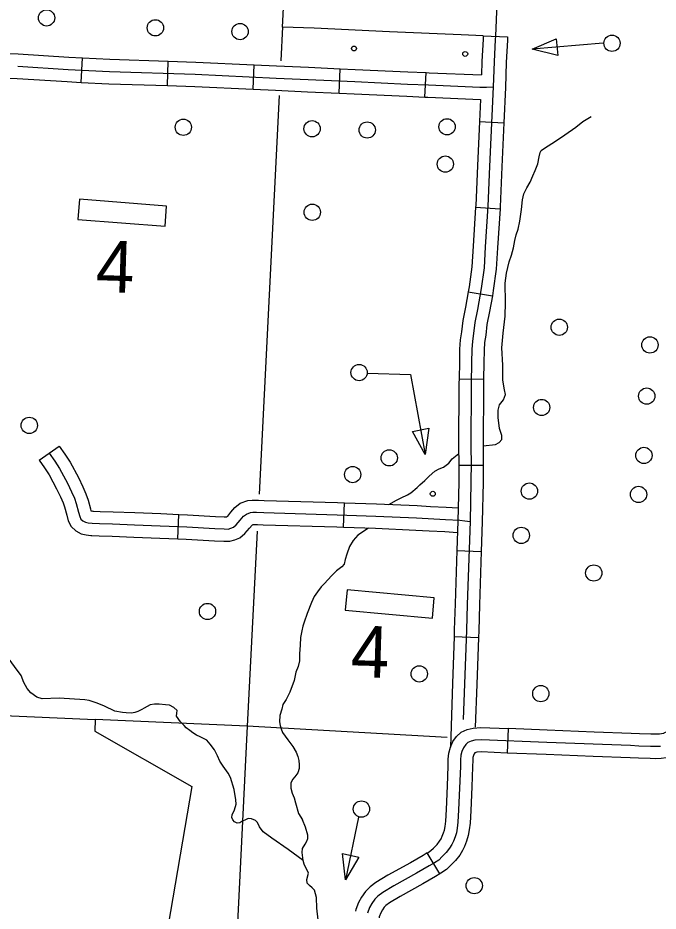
# Model space of a CAD drawing. Extents: x 653372 to 905732, y 627442 to 787275.
# Drawn here: x 673522 to 677453, y 779033 to 784516 of the extents above; entities that cross this region are included whole.
import ezdxf

# ---------------------------------------------------------------- set-up
doc = ezdxf.new("R2010")
doc.units = 0
for name, color, linetype in [('31', 7, 'Continuous'), ('32', 7, 'Continuous'), ('34', 7, 'Continuous'), ('35', 7, 'Continuous'), ('45', 7, 'Continuous'), ('5', 7, 'Continuous'), ('56', 7, 'Continuous'), ('57', 7, 'Continuous'), ('6', 7, 'Continuous')]:
    doc.layers.add(name, color=color, linetype=linetype)

msp = doc.modelspace()

# ---------------------------------------------------------------- linework, layer by layer
at = {"layer": '31'}
for p, q in [((676532.4, 780153.5), (676526.2, 780003.7)), ((676159.4, 779803.2), (676159.4, 779803.2)), ((676112.4, 779261.3), (676035.8, 779390.3))]:
    msp.add_line(p, q, dxfattribs=at)
for points in [[(676159.4, 779803.2), (676164.4, 779922.8), (676164.9, 779966.4), (676168, 780002.5), (676177.5, 780039.1), (676193.7, 780073.7), (676214.7, 780104.8), (676243.3, 780131.4), (676280.2, 780148.5), (676317.7, 780157), (676365.4, 780160.5), (676532.4, 780153.5)], [(677059.7, 780132.8), (676772.4, 780143.5), (676532.4, 780153.5)], [(677499.4, 780133.8), (677498.1, 780131.3), (677496.9, 780130.1), (677488.4, 780125.1), (677486.6, 780124.4), (677473.9, 780120.9), (677461.8, 780119.5), (677439, 780118.9), (677409, 780119.8), (677338.1, 780121.1), (677288.4, 780124.2), (677059.7, 780132.8)], [(677467.2, 780044.6), (677438.9, 780043.8), (677407.2, 780044.8), (677335.1, 780046.2), (677284.7, 780049.2), (676769.4, 780068.6), (676366.5, 780085.4), (676328.8, 780082.6), (676304.5, 780077.1), (676285.7, 780068.4), (676272, 780055.7), (676259.1, 780036.6), (676248.3, 780013.6), (676242.2, 779989.8), (676239.8, 779962.7), (676239.3, 779920.8), (676228.2, 779654.1), (676223.7, 779579.7), (676219.4, 779542.6), (676214.7, 779514), (676207, 779488.7), (676196.1, 779461.8), (676186.2, 779442), (676173.1, 779419.8), (676152.1, 779393.3), (676127.3, 779367.7), (676106.5, 779346.6), (676080.4, 779329.5), (676048, 779310.3), (675970.6, 779265.3), (675831.4, 779188.5), (675762.7, 779147.1), (675733.3, 779124.7), (675713.3, 779105.9), (675696.3, 779080), (675681.6, 779054.8), (675669.7, 779020.3)], [(677631.5, 780062.8), (677621.3, 780043.8), (677592, 780011.8), (677554.8, 779990.2), (677534.9, 779982.1), (677502.5, 779973.3), (677472.6, 779969.7), (677438.8, 779968.8), (677405.3, 779969.8), (677332.1, 779971.2), (677281, 779974.3), (677054.1, 779982.9)], [(676526.2, 780003.7), (676367.7, 780010.2), (676339.8, 780008.2), (676328.9, 780005.7), (676328.7, 780005.7), (676324.5, 779999.4), (676319.2, 779988.1), (676316.4, 779977.1), (676314.8, 779959), (676314.3, 779918.8), (676309.2, 779797)], [(677054.1, 779982.9), (676766.5, 779993.7), (676526.2, 780003.7)], [(676035.8, 779390.3), (676040.7, 779393.2), (676058.7, 779405), (676073.7, 779420.1), (676095.6, 779442.8), (676111.1, 779462.4), (676120.2, 779477.8), (676127.7, 779492.7), (676136.2, 779513.8), (676141.5, 779531.2), (676145.1, 779553), (676148.9, 779586.3), (676153.3, 779658), (676159.4, 779803.2)], [(676309.2, 779797), (676303.1, 779650.2), (676298.4, 779573.2), (676293.7, 779532.2), (676287.9, 779496.9), (676277.7, 779463.6), (676264.5, 779431), (676252.1, 779406.1), (676235.1, 779377.3), (676208.6, 779343.9), (676181, 779315.3), (676154.3, 779288.2), (676120.1, 779265.8), (676112.4, 779261.3)], [(676035.8, 779390.3), (676010, 779375), (675933.7, 779330.5), (675793.9, 779253.4), (675720.5, 779209.2), (675684.7, 779181.9), (675655.6, 779154.5), (675632.6, 779119.6), (675613.1, 779086.3), (675598.1, 779042.7), (675595.4, 779033.2)], [(676112.4, 779261.3), (676086, 779245.6), (676007.6, 779200), (675868.9, 779123.5), (675804.9, 779084.9), (675781.9, 779067.4), (675771.1, 779057.3), (675760, 779040.4), (675750, 779023.4), (675741.2, 778997.8), (675739.7, 778992.2)]]:
    msp.add_lwpolyline(points, dxfattribs=at)
at = {"layer": '32'}
for p, q in [((676379.4, 784406.7), (676529.2, 784400.3)), ((673911.2, 784120.6), (673918.7, 784270.4)), ((674440.1, 784100.4), (674445, 784250.3)), ((674966.5, 784078.1), (674973.6, 784227.9)), ((675494.2, 784054.5), (675500.9, 784204.3)), ((676021.6, 784030.4), (676028.3, 784180.3)), ((676355.8, 783879.4), (676505.6, 783872.7)), ((676333, 783353.7), (676482.7, 783343.4)), ((676287.5, 782835.7), (676435.4, 782810.3)), ((676230.9, 782300.9), (676380.9, 782297.6)), ((676229.7, 781771.7), (676379.7, 781770.9)), ((676217.8, 781246), (676367.7, 781240.9)), ((676200.4, 780718.4), (676350.3, 780713))]:
    msp.add_line(p, q, dxfattribs=at)
for points in [[(676379.4, 784406.7), (676378.5, 784386.3), (676370.9, 784249.4), (676367.9, 784165.9)], [(676454.3, 784403.5), (676453.4, 784382.7), (676445.8, 784246), (676440.3, 784092.4), (676418.6, 783604.2), (676408.7, 783361.4), (676391.5, 783110.1)], [(676529.2, 784400.3), (676528.3, 784379), (676520.7, 784242.6), (676515.3, 784089.4), (676505.6, 783872.7)], [(673384.7, 784297.2), (673412.9, 784298.4), (673524.8, 784295), (673834.4, 784274.7), (673918.7, 784270.4)], [(673918.7, 784270.4), (674087, 784261.9), (674445, 784250.3)], [(673521.2, 784220.1), (673830, 784199.8), (674083.9, 784187), (674611.5, 784169.9), (675107.3, 784146.6), (675303.7, 784138.1), (675590.3, 784125.3), (675914, 784110.4), (676043.4, 784104.5), (676359.4, 784091.2), (676399.5, 784091.9), (676440.3, 784092.4)], [(674445, 784250.3), (674614.5, 784244.8), (674973.6, 784227.9)], [(674973.6, 784227.9), (675110.7, 784221.5), (675307, 784213), (675500.9, 784204.3)], [(675500.9, 784204.3), (675593.7, 784200.2), (675917.4, 784185.3), (676028.3, 784180.3)], [(673402.9, 784148.6), (673517.6, 784145.1), (673825.7, 784124.9), (673911.2, 784120.6)], [(676028.3, 784180.3), (676046.7, 784179.5), (676367.9, 784165.9)], [(673911.2, 784120.6), (674080.8, 784112.1), (674440.1, 784100.4)], [(674440.1, 784100.4), (674608.6, 784094.9), (674966.5, 784078.1)], [(674966.5, 784078.1), (675103.9, 784071.6), (675300.4, 784063.1), (675494.2, 784054.5)], [(675494.2, 784054.5), (675586.9, 784050.3), (675910.6, 784035.4), (676021.6, 784030.4)], [(676021.6, 784030.4), (676040.1, 784029.6), (676361.9, 784016)], [(676361.9, 784016), (676355.8, 783879.4)], [(676355.8, 783879.4), (676343.7, 783607.4), (676333.8, 783365.5), (676333, 783353.7)], [(676505.6, 783872.7), (676493.6, 783601), (676483.6, 783357.3), (676482.7, 783343.4)], [(676333, 783353.7), (676316.7, 783114.7), (676309.9, 782989.1), (676292.7, 782865.8), (676287.5, 782835.7)], [(676482.7, 783343.4), (676466.4, 783105.6), (676459.4, 782974.7), (676440.9, 782842.7), (676435.4, 782810.3)], [(676391.5, 783110.1), (676384.7, 782981.9), (676366.8, 782854.2), (676345, 782727), (676328.5, 782646.4), (676320.5, 782579.5), (676313.1, 782531.6), (676309.5, 782479.7), (676308.1, 782400.6), (676305.3, 782272.4), (676303.4, 781874.9), (676304.8, 781787.7), (676304.1, 781665.5), (676298.9, 781424.3), (676281.6, 780916.4), (676276.8, 780757.3), (676264.9, 780427.6), (676256.9, 780209.9)], [(676287.5, 782835.7), (676271.3, 782740.9), (676254.4, 782658.3), (676246.2, 782589.7), (676238.5, 782540), (676234.6, 782482.9), (676233.1, 782402), (676230.9, 782300.9)], [(676435.4, 782810.3), (676418.7, 782713.2), (676402.6, 782634.4), (676394.8, 782569.3), (676387.7, 782523.3), (676384.5, 782476.4), (676383.1, 782399.1), (676380.9, 782297.6)], [(676230.9, 782300.9), (676230.3, 782273.4), (676228.4, 781874.5), (676229.8, 781787.3), (676229.7, 781771.7)], [(676380.9, 782297.6), (676380.3, 782271.4), (676378.4, 781875.3), (676379.8, 781788.1), (676379.7, 781770.9)], [(676229.7, 781771.7), (676229.1, 781666.6), (676223.9, 781426.4), (676217.8, 781246)], [(676379.7, 781770.9), (676379.1, 781664.5), (676373.8, 781422.2), (676367.7, 781240.9)], [(676217.8, 781246), (676206.6, 780918.8), (676201.9, 780759.8), (676200.4, 780718.4)], [(676367.7, 781240.9), (676356.6, 780914), (676351.8, 780754.8), (676350.3, 780713)], [(676200.4, 780718.4), (676190, 780430.3), (676177.5, 780039.1)], [(676350.3, 780713), (676339.9, 780424.8), (676330.2, 780161.9)]]:
    msp.add_lwpolyline(points, dxfattribs=at)
at = {"layer": '34'}
msp.add_lwpolyline([(676593.1, 786729.9), (676561.3, 786090.6), (676516.4, 785413.5), (676500.9, 785202.7), (676475.4, 784823.6), (676462.8, 784604.8), (676454.3, 784403.5)], dxfattribs=at)
at = {"layer": '35'}
for points in [[(676514, 782686), (676516.9, 782768.4), (676513.8, 782886.9), (676522.5, 782948.5), (676539, 783018.8), (676552.1, 783059), (676564.7, 783105.6), (676573.9, 783148.9), (676582, 783185.4), (676593.5, 783218.9), (676603.6, 783268.9), (676614, 783339.2), (676620.7, 783399.5), (676628.4, 783436.2), (676647.5, 783473.8), (676666.8, 783507.8), (676683.2, 783546), (676698.2, 783579.7), (676714.3, 783620.6), (676723.4, 783662.6), (676728.3, 783689.4), (676736.2, 783701.4), (676760.9, 783720.4), (676817.9, 783755.6), (676880.6, 783797.4), (676948.1, 783845.8), (676991.2, 783879.9), (677042.4, 783910.3)], [(676378.1, 781890), (676455.3, 781897.8), (676478.3, 781909.8), (676493.5, 781929), (676494.1, 781952.8), (676480.2, 781996), (676471.5, 782064.1), (676471.9, 782108.7), (676478.9, 782141), (676503.7, 782171.5), (676515.3, 782204.3), (676511, 782232.8), (676499.6, 782293.5), (676498.9, 782384.2), (676494.6, 782491.5), (676502.7, 782580.2), (676514, 782686)], [(675800.3, 781529.8), (675847.6, 781556.8), (675876.2, 781570.8), (675915, 781588.8), (675935.7, 781601.7), (675973, 781633.3), (675990.5, 781649.1), (676021.9, 781677), (676047.2, 781703.7), (676081.5, 781733.9), (676108.6, 781747.9), (676136.4, 781758.9), (676167.6, 781784), (676189.2, 781810.1), (676228.9, 781841.4)], [(675674.7, 781384.8), (675609, 781342), (675581.7, 781309.3), (675558.8, 781272.4), (675542.2, 781224.2), (675532, 781190.9), (675524.6, 781162.8), (675511.6, 781146.8), (675477.5, 781121.2), (675449.1, 781093.7), (675424.6, 781066.8), (675404.1, 781043.7), (675383.8, 781023.9), (675361.1, 780993), (675341.8, 780964.6), (675325.6, 780926.9), (675299.2, 780861.2), (675280.5, 780806.4), (675271.8, 780781.7), (675265.1, 780754.7), (675257.3, 780712.8), (675255.9, 780666.1), (675251.6, 780613.6), (675250.3, 780569.5), (675244, 780534.1), (675229.8, 780501), (675217.7, 780448.8), (675192.5, 780376.5), (675170.1, 780332.3), (675149.5, 780302), (675142, 780272.6), (675130.7, 780235.1), (675129.5, 780195), (675132.1, 780171.8), (675138.1, 780153.2), (675147.3, 780130.6), (675163.7, 780107.7), (675180.1, 780084.8), (675210.5, 780044.4), (675231.2, 780009.5), (675241.6, 779982.9), (675248.1, 779957), (675249.9, 779931.7), (675249.9, 779909.2), (675240.6, 779882.5), (675223.4, 779858), (675207.7, 779840.8), (675198.5, 779817.9), (675198.2, 779789), (675207.2, 779757.8), (675218.1, 779727.8), (675225.8, 779697.9), (675245.5, 779631.6), (675270, 779593.3)], [(673933.7, 780329.9), (673775, 780340.4), (673670.9, 780336), (673638.1, 780346.1), (673601.3, 780372.8), (673579.5, 780400.5), (673559.5, 780435.8), (673542.7, 780480), (673500.7, 780535.5), (673451.5, 780601.7), (673406.7, 780664.9), (673349.8, 780726.8), (673303, 780770.4), (673284.3, 780802.6), (673281.5, 780818.2)], [(675273.6, 779343.8), (675180.9, 779411.7), (675081.5, 779481.1), (675027.7, 779519.7), (675004.9, 779549.8), (674992.4, 779577.7), (674980.5, 779590.4), (674956.1, 779600.6), (674935.3, 779602.2), (674922.8, 779596), (674897.7, 779582.5), (674885.2, 779575.3), (674868, 779572.9), (674853.1, 779581.9), (674842.1, 779594.6), (674834.9, 779608.1), (674838.3, 779625.1), (674851.5, 779654.1), (674862, 779688.9), (674860.9, 779715.5), (674851, 779778.9), (674827.6, 779853.6), (674813.2, 779879.6), (674782.3, 779923.3), (674762.3, 779954.2), (674748.1, 779986.9), (674729.3, 780022.6), (674701.9, 780057.6), (674681.8, 780082.8), (674641.6, 780104), (674619.2, 780114.1), (674595.8, 780127.2), (674577.3, 780141.9), (674556, 780157.8), (674543.1, 780172.4), (674521.5, 780194.6), (674496.9, 780229.5), (674498.5, 780249.4), (674499.9, 780265.5), (674478.7, 780284.1), (674452.5, 780297.3), (674427.9, 780299.9), (674390.1, 780302.9), (674361.6, 780302.8), (674334, 780298.9), (674298.3, 780280.1), (674283.8, 780271), (674258.8, 780258.5), (674240.6, 780253.3), (674220.5, 780248.3), (674186.5, 780250.2), (674164.7, 780251.8), (674116.6, 780259.9), (674054.9, 780291.2), (674009.9, 780310.6), (673984.5, 780317), (673960.1, 780325.3), (673933.7, 780329.9)], [(675365.1, 778980.6), (675358.7, 779051), (675355.9, 779117.5), (675343, 779161.6), (675329.3, 779177.2), (675311.7, 779191), (675298.8, 779204.6), (675296.6, 779226.5), (675307.3, 779266.9), (675280.5, 779320.8), (675273.6, 779343.8), (675268.4, 779393.3), (675270.1, 779417.9), (675287, 779444), (675296.1, 779463.6), (675302.3, 779479.1), (675301.9, 779499.1), (675287.3, 779547.9), (675270, 779593.3)]]:
    msp.add_lwpolyline(points, dxfattribs=at)
at = {"layer": '45'}
for p, q in [((673653.6, 781800.7), (673776.3, 781887)), ((675521.6, 781390.3), (675527, 781540.2)), ((674503.8, 781318.6), (674510.2, 781468.4))]:
    msp.add_line(p, q, dxfattribs=at)
for points in [[(673776.3, 781887), (673810.6, 781838.3), (673842.3, 781789.2), (673894.1, 781694.2), (673920.4, 781638.3), (673940.1, 781594.8), (673952.9, 781556.7), (673967, 781502.2), (673969.9, 781491.1), (673985, 781488.9), (673982.8, 781489)], [(673653.6, 781800.7), (673686.3, 781754.2), (673713.4, 781712.4), (673760.2, 781626.4), (673784.2, 781575.4), (673800.4, 781539.7), (673809, 781514.1), (673821.9, 781464.1), (673831.4, 781428.6), (673849.1, 781393.5), (673877.9, 781368.1), (673911, 781349.5), (673941.7, 781343.6), (673970.9, 781339.4), (673976.1, 781339.2)], [(673714.9, 781843.8), (673748.4, 781796.2), (673777.9, 781750.8), (673827.2, 781660.3), (673852.3, 781606.8), (673870.3, 781567.2), (673880.9, 781535.4), (673894.4, 781483.1), (673901.8, 781455.5), (673909.6, 781440.2), (673921.6, 781429.6), (673937.1, 781420.9), (673954.1, 781417.6), (673978, 781414.2), (674023.8, 781412.1), (674103.5, 781409.7), (674237.6, 781404.3), (674396.2, 781398.2), (674559.4, 781391.3), (674732.3, 781381.3), (674788, 781378.9), (674814, 781378.8), (674829.2, 781383.2), (674845.8, 781390.2), (674863.4, 781404.7), (674887.5, 781433.5), (674907.4, 781456.8), (674924.9, 781470.7), (674950.6, 781480.2), (674964.4, 781481.6)], [(674510.2, 781468.4), (674563.2, 781466.2), (674736.1, 781456.2), (674789.7, 781453.9), (674803.6, 781453.9), (674804.2, 781454), (674806.5, 781455), (674810.3, 781458.2), (674830.3, 781481.9), (674855.1, 781511.1), (674887.7, 781536.9), (674933.4, 781553.8), (674960.7, 781556.7), (674988.3, 781556.5), (674999.7, 781556)], [(674999.7, 781556), (675033.9, 781554.6), (675484.7, 781541.7), (675527, 781540.2)], [(675527, 781540.2), (675723.5, 781533.2), (675973.8, 781522.2), (676055.9, 781517.8)], [(676055.9, 781517.8), (676152, 781512.6), (676225.7, 781508.1)], [(673982.8, 781489), (674026.6, 781487.1), (674106.2, 781484.7), (674240.5, 781479.3), (674399.3, 781473.1), (674510.2, 781468.4)], [(674964.4, 781481.6), (674986.5, 781481.5), (675031.3, 781479.6), (675482.3, 781466.8), (675720.5, 781458.2), (675970.1, 781447.3), (676147.6, 781437.7), (676236.7, 781432.3), (676265.9, 781429.3), (676298.9, 781424.3)], [(674503.8, 781318.6), (674555.6, 781316.4), (674728.6, 781306.4), (674786.3, 781303.9), (674824.4, 781303.8), (674854.2, 781312.3), (674885.2, 781325.4), (674916.5, 781351.3), (674944.8, 781385), (674959.7, 781402.6), (674962.2, 781404.5), (674967.8, 781406.6), (674968.1, 781406.6), (674984.7, 781406.5), (674993.4, 781406.2)], [(674993.4, 781406.2), (675028.6, 781404.7), (675479.8, 781391.8), (675521.6, 781390.3)], [(675521.6, 781390.3), (675717.5, 781383.3), (675966.5, 781372.3), (676047.8, 781368)], [(676047.8, 781368), (676143.3, 781362.9), (676221.6, 781358.1)], [(673976.1, 781339.2), (674021, 781337.2), (674100.9, 781334.8), (674234.6, 781329.4), (674393.2, 781323.3), (674503.8, 781318.6)]]:
    msp.add_lwpolyline(points, dxfattribs=at)
at = {"layer": '5'}
for points in [[(675147.7, 784461.6), (675137.1, 784252.8)], [(675126.3, 784039.5), (675002.7, 781592.3)], [(674991.2, 781365), (674930.7, 780168.6)], [(674930.7, 780168.6), (673997.2, 780209.2)], [(674930.7, 780168.6), (674845, 778418.5)], [(676159, 780099.4), (674930.7, 780168.6)]]:
    msp.add_lwpolyline(points, dxfattribs=at)
at = {"layer": '56'}
for p, q in [((676680, 784324.8), (676828.3, 784388.1)), ((676828.3, 784388.1), (676836.7, 784286.4)), ((676836.7, 784286.4), (676680, 784324.8)), ((675946, 781978.4), (676046.3, 781996.9)), ((676023.9, 781837.2), (675946, 781978.4)), ((676046.3, 781996.9), (676023.9, 781837.2)), ((675533.2, 779226.2), (675515.1, 779386.5)), ((675515.1, 779386.5), (675614.8, 779365.3)), ((675614.8, 779365.3), (675533.2, 779226.2))]:
    msp.add_line(p, q, dxfattribs=at)
for points in [[(677116.8, 784360.6), (676680, 784324.8)], [(675668.5, 782336), (675933.2, 782327.8), (676023.9, 781837.2)], [(675614.5, 779609.2), (675533.2, 779226.2)]]:
    msp.add_lwpolyline(points, dxfattribs=at)
for centre, radius in [((673698.2, 784516.3), 50), ((674366.5, 784455.2), 50), ((674886.2, 784432.5), 50), ((677170.1, 784360.6), 50), ((675585.9, 784328.6), 15), ((676269, 784295), 15), ((674537.9, 783844.7), 50), ((675328.7, 783835.7), 50), ((675667, 783828.2), 50), ((676157.4, 783847.6), 50), ((676146.7, 783618.5), 50), ((675329.7, 783322.9), 50), ((676846.5, 782617.5), 50), ((677403.2, 782508.8), 50), ((675617.4, 782339.1), 50), ((677383.2, 782194.5), 50), ((676738.2, 782124.8), 50), ((673592, 782014.7), 50), ((675802.1, 781815.7), 50), ((677366, 781830.3), 50), ((675577.7, 781713), 50), ((676662.8, 781611.4), 50), ((677333.1, 781590.8), 50), ((676069.5, 781595.2), 15), ((676613.1, 781339.5), 50), ((677058.3, 781108.8), 50), ((674686.4, 780872.6), 50), ((675986.6, 780489.6), 50), ((676733.1, 780368.5), 50), ((675631.7, 779659.9), 50), ((676324.2, 779189.6), 50)]:
    msp.add_circle(centre, radius, dxfattribs=at)
at = {"layer": '57'}
for p, q in [((673899.6, 783403.7), (673889.8, 783279.1)), ((674435.5, 783361.4), (673899.6, 783403.7)), ((674425.6, 783236.8), (674435.5, 783361.4)), ((673889.8, 783279.1), (674425.6, 783236.8)), ((675543.4, 781005.7), (675531.8, 780881.3)), ((676078.6, 780955.9), (675543.4, 781005.7)), ((676067, 780831.4), (676078.6, 780955.9)), ((675531.8, 780881.3), (676067, 780831.4))]:
    msp.add_line(p, q, dxfattribs=at)
at = {"layer": '6'}
for points in [[(676379.6, 784406.7), (676244.7, 784412.5), (675804.8, 784431.3), (675341.1, 784452.6), (675147.6, 784459.5), (675199.4, 785484.8), (672532.7, 785573.2), (672511.2, 784852)], [(672247.2, 779726.4), (672376.8, 779728.7), (672525, 779840.9), (672648.1, 779840.9), (672735.1, 780264.2), (673997.2, 780209.2), (673993.7, 780137), (674589.2, 779798), (674431.5, 778863.2)]]:
    msp.add_lwpolyline(points, dxfattribs=at)

# ---------------------------------------------------------------- texts
at = {"layer": '57'}
for p in [(673997.9, 782834.7), (675563.5, 780470.7)]:
    msp.add_text('4', height=316.8, rotation=358.28, dxfattribs=at).set_placement(p)

doc.saveas('drawing.dxf')
